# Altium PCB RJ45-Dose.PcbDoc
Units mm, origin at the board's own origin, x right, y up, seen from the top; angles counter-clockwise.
Board outline 33.93 x 32 mm, 2 copper layers (Top Layer, Bottom Layer), stack 1.601 mm thick; 9 components, 4 nets, 22 pads, 0 vias.
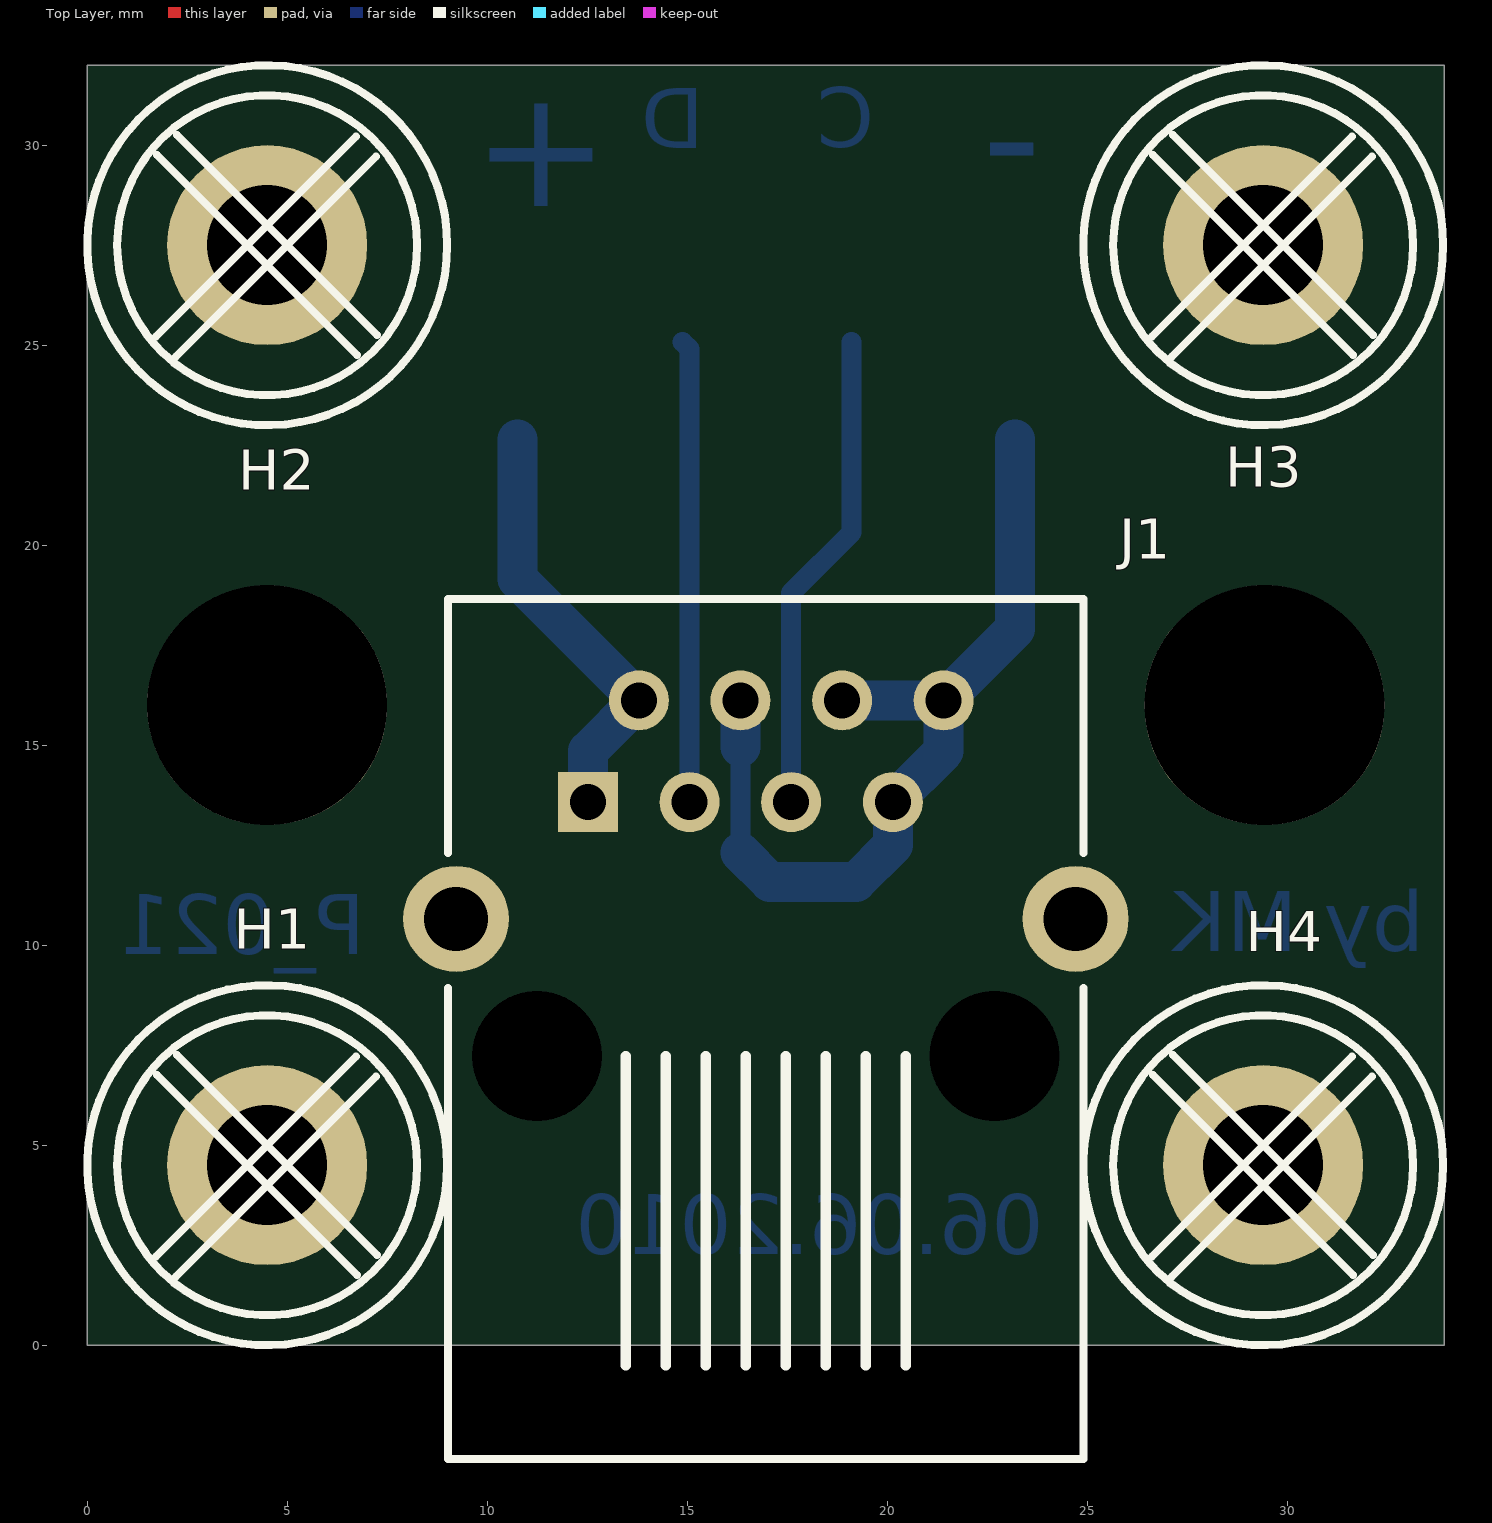
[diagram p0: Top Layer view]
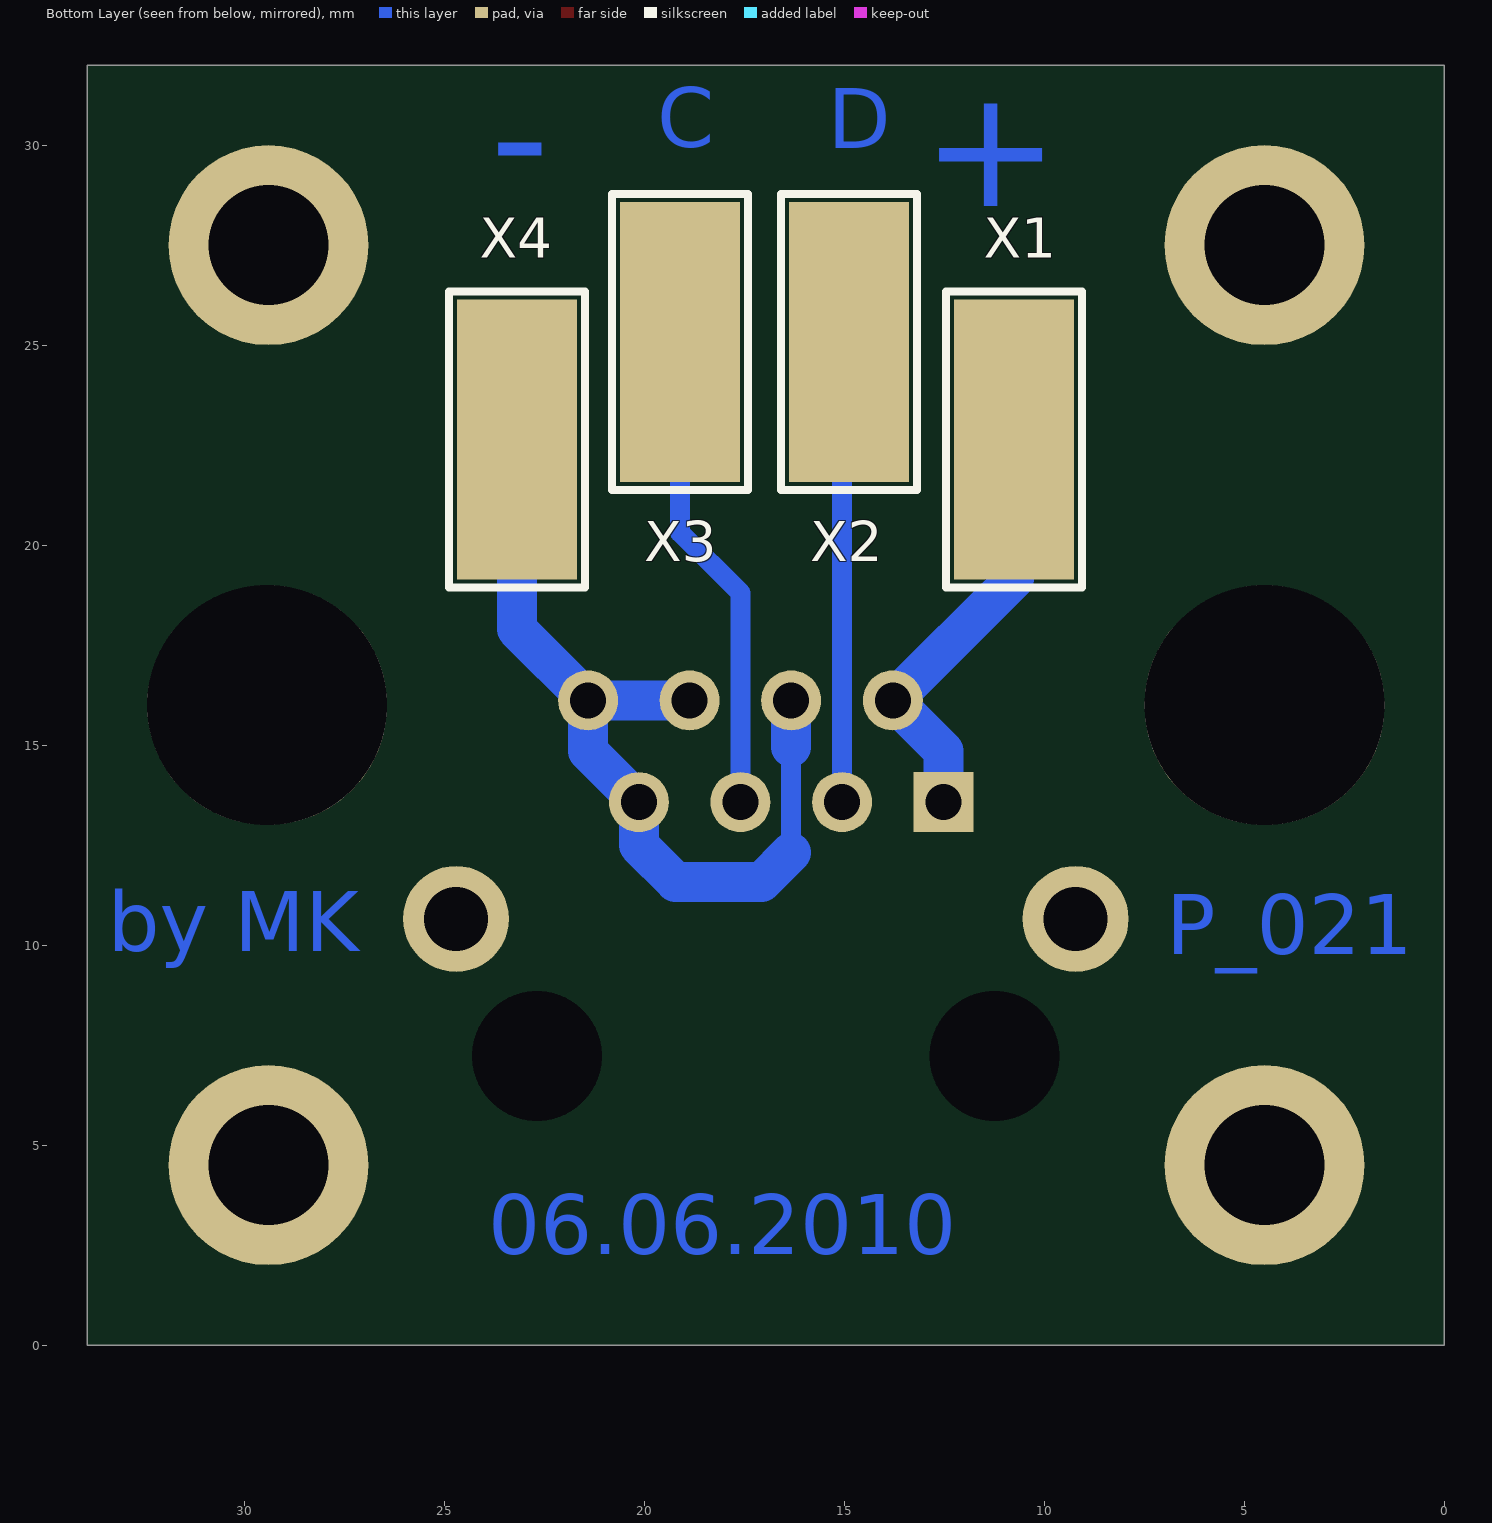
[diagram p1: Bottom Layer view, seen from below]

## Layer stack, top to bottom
Top Layer: signal copper 0.0356
Dielectric: core 1.53, FR-4, Dk 4.8
Bottom Layer: signal copper 0.0356

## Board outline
0,0 33.93,0 33.93,32 0,32

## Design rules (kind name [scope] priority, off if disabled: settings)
Clearance [All] p1: gap=0.2
ComponentClearance [All] p1 off: gap=0.254 collisioncheckmode=3 verticalgap=0.254 showdistances=FALSE
HoleSize [All] p1: absolutevalues=TRUE maxlimit=4 minlimit=0.025 maxpercent=80.000 minpercent=20.000
PlaneConnect [All] p1: planeconnectstyle=Relief reliefexpansion=0.5 reliefentries=4 reliefconductorwidth=0.2 reliefairgap=0.2
PolygonConnect [All] p1: connectstyle=Direct reliefconductorwidth=1 reliefentries=4 polygonreliefangle="90 Angle"
RoutingVias [All] p1: holewidth=0.5 width=0.9 viastyle="Through Hole" minholewidth=0.4 minwidth=0.8 maxholewidth=0.711 maxwidth=1.27
SolderMaskExpansion [All] p1: expansion=0.102
TestPointUsage [All] p1: valid=0 allowmultiple=FALSE
Testpoint [All] p1: side=15 testpointundercomponent=TRUE minsize=1.016 maxsize=2.54 preferedsize=1.524 minholesize=0 maxholesize=1.016 preferedholesize=0.813 testpointgrid=0.025 style=1023 order=0-112345678
Width [All] p1: maxlimit=10 minlimit=0.2 preferedwidth=0.5
16 further rules are at their usual default settings.

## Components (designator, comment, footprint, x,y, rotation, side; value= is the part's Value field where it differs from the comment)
H1 "Hole 3mm" "Hole 3,5mm" 4.5,4.5 r0 top
H2 "Hole 3mm" "Hole 3,5mm" 4.5,27.5 r0 top
H3 "Hole 3mm" "Hole 3,5mm" 29.4,27.5 r0 top
H4 "Hole 3mm" "Hole 3,5mm" 29.4,4.5 r0 top
J1 "MEBP 8-8G" "RJ45-JACK-MEBP 8-8G" 12.52,13.58 r0 top
X1 "Ground" GND_PAD3 10.76,22.64 r90 bottom
X2 "Ground" GND_PAD3 14.88,25.08 r90 bottom
X3 "Ground" GND_PAD3 19.11,25.08 r90 bottom
X4 "Ground" GND_PAD3 23.19,22.64 r90 bottom

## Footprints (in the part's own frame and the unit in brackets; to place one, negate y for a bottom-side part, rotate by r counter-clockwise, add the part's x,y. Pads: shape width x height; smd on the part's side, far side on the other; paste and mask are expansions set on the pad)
GND_PAD3 [mm]
  rect 7x3 smd: 1(0,0)
  silkscreen extent -3.7,-1.7 3.7,1.7
"Hole 3,5mm" [mm]
  round 5 hole 3: 1(0,0)
  silkscreen extent -4.5,-4.5 4.5,4.5
"RJ45-JACK-MEBP 8-8G" [mm] "Connector; PCB Jack, Thru-Hole; 1-Port, 8 Positions, 8 Loaded; Shielded without Lightpipes; Left Angle"
  rect 1.5x1.5 hole 0.9: 1(0,0)
  round 1.5 hole 0.9: 2(1.27,2.54) 3(2.54,0) 4(3.81,2.54) 5(5.08,0) 6(6.35,2.54) 7(7.62,0) 8(8.89,2.54)
  round 2.65 hole 1.6: MH1(-3.3,-2.921) MH2(12.19,-2.921)
  round 2.95 hole 3.25: MH3(-1.27,-6.35) MH4(10.16,-6.35)
  silkscreen extent -3.49,-16.42 12.38,5.08

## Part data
H1 H2 H3 H4: library part "Hole 3,5mm"
J1: library part "RJ45-JACK-MEBP 8-8G", "Right Angle, Standard Profile, External Shield PCB Jack"
X1 X2 X3 X4: library part GND_PAD3, "Groundpad"

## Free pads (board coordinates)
  round 6 hole 6 unplated: 0(4.5,16) 1(29.43,16)

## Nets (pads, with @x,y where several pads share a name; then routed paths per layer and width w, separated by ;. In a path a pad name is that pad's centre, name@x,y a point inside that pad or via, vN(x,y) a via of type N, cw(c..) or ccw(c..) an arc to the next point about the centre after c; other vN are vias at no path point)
CLOCK: J1.5 X3.1 | length 12.1
  Bottom Layer w0.5: J1.5 17.6,18.81 19.11,20.32 X3.1
DATA: J1.3 X2.1 | length 11.6
  Bottom Layer w0.5: X2.1 15.06,24.9 J1.3
GND: J1.4 J1.6 J1.7 J1.8 X4.1 | length 22.2
  Bottom Layer w0.5: 16.33,12.32 16.33,14.95
  Bottom Layer w1: 16.33,12.32 17.07,11.58 19.22,11.58 20.14,12.5 J1.7 21.41,14.85 J1.8 ; 16.33,14.95 J1.4 ; J1.6 J1.8 ; X4.1 23.19,17.9 J1.8
VCC_1,55V: J1.1 J1.2 X1.1 | length 10.8
  Bottom Layer w1: X1.1 10.76,19.15 J1.2 12.52,14.85 J1.1
pads on no net: H1.1 H2.1 H3.1 H4.1 J1.MH1 J1.MH2 J1.MH3 J1.MH4

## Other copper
Top Layer:
  text "2" at 133.038,-89.66 h1.27
  text "Top Layer" at 145.618,-89.76 h1.27
Bottom Layer:
  text "C" at 19.68,29.95 h1.5
  text "D" at 15.42,29.92 h1.5
  text "-" at 22.37,28.77 h3
  text "+" at 9.62,28.48 h3
  text "by MK" at 33.42,9.85 h1.5
  text "P_021" at 6.95,9.78 h1.5
  text "06.06.2010" at 23.91,2.27 h1.5
  text "3" at 133.038,-89.66 h1.27
  text "Bottom Layer" at 145.618,-89.76 h1.27

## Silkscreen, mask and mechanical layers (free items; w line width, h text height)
Top Overlay:
  text "1" at 133.208,-89.65 h1.27
  text "Top Overlay" at 145.618,-89.76 h1.27
Bottom Overlay:
  text "4" at 133.038,-89.66 h1.27
  text "Bottom Overlay" at 145.618,-89.76 h1.27
Mechanical 1:
  the board outline again, w0.2
Mechanical 16:
  lines w0.127: -111.96,-47.38 -106.88,-47.38 ; -111.96,0.88 -106.88,0.88 ; -111.96,49.14 -106.88,49.14 ; -41.96,-95.64 -41.96,-90.56 ; -41.96,92.32 -41.96,97.4 ; 28.04,-95.64 28.04,-90.56 ; 28.04,92.32 28.04,97.4 ; 98.04,-95.64 98.04,-90.56 ; 98.04,92.32 98.04,97.4 ; 162.96,-47.38 168.04,-47.38 ; 162.96,0.88 168.04,0.88 ; 162.96,49.14 168.04,49.14 ; -111.96,-95.64 168.04,-95.64 168.04,97.4 -111.96,97.4 -111.96,-95.64 ; -106.88,-90.56 -106.88,92.32 162.96,92.32 162.96,-90.56 -106.88,-90.56
  lines w0.2: 0.127,-90.361 0.127,-70.549 67.881,-70.572 ; 67.899,-90.56 67.899,-70.56 162.899,-70.56 ; 67.899,-87.56 144.899,-87.56 162.899,-87.56 ; 67.899,-84.56 124.899,-84.56 ; 67.899,-79.56 124.899,-79.56 ; 77.899,-84.56 77.899,-79.56 ; 109.855,-87.56 109.855,-79.56 ; 124.899,-90.56 124.899,-70.56 ; 144.899,-90.56 144.899,-70.56
  text "1" at -75.714,93.971 h1.78
  text "2" at -3.07,93.971 h1.78
  text "3" at 70.082,93.971 h1.78
  text "4" at 142.98,93.971 h1.78
  text "A" at -110.055,70.959 h1.78
  text "A" at 164.865,70.959 h1.78
  text "B" at -110.055,22.902 h1.78
  text "B" at 164.865,22.902 h1.78
  text "C" at -110.055,-25.612 h1.78
  text "C" at 164.865,-25.612 h1.78
  text "D" at -110.055,-73.618 h1.78
  text "D" at 164.865,-73.618 h1.78
  text "Copying of this document, and giving it to others and the use or comunication of the" at 1.321,-73.876 h1
  text "RJ45-Dose" at 70.488,-75.74 h2.27
  text "contents therof, ar forbidden without express authority. Offenders are liable to the" at 1.321,-75.908 h1
  text "payment of damages. All rights are reserved in the event of the grant of a patent or" at 1.321,-77.94 h1
  text "the registration of a utility model or design." at 1.321,-79.972 h1
  text "by MK" at 147.04,-80.85 h3
  text "Weitergabe sowie vervielfaeltigung dieser Unterlage, Verwertung und Mitteilung ihres Inhalts" at 1.321,-82.512 h1
  text "Size:" at 68.599,-82.76 h1.27
  text "A4" at 73.899,-82.76 h1.27
  text "Number:" at 78.699,-82.76 h1.27
  text "Revision: 1.0" at 110.989,-82.76 h1.27
  text "1.0" at 89.8,-82.91 h1.27
  text "nicht gestattet, soweit nicht ausdruecklich zugestanden. Zuwiederhandlung verpflichtet zu" at 1.321,-84.544 h1
  text "Schadensersatz. Alle Rechte fuer den Fall der Patenterteilung oder Gebrauchsmuster-" at 1.321,-86.576 h1
  text ".Pcb_File_Name_No_Path" at 68.599,-86.66 h1.27
  text "Project: P_021" at 110.989,-86.824 h1.27
  text "Eintragungen vorbehalten." at 1.321,-88.608 h1
  text "Print Date:" at 93.5,-89.59 h1.27
  text "Date:" at 68.599,-89.66 h1.27
  text "06.06.2010" at 74.399,-89.66 h1.27
  text ".Print_Date" at 105.119,-89.66 h1.27
  text "Sheet    of 4" at 126.399,-89.66 h1.27
  text "1" at -75.714,-93.989 h1.78
  text "2" at -3.07,-93.989 h1.78
  text "3" at 70.082,-93.989 h1.78
  text "4" at 142.98,-93.989 h1.78

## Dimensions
0,0 to 33.93,0 on Mechanical 14
0,0 to 0,32 on Mechanical 14
4.5,27.5 to 29.4,27.5 on Mechanical 14
4.5,4.5 to 4.5,27.5 on Mechanical 14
